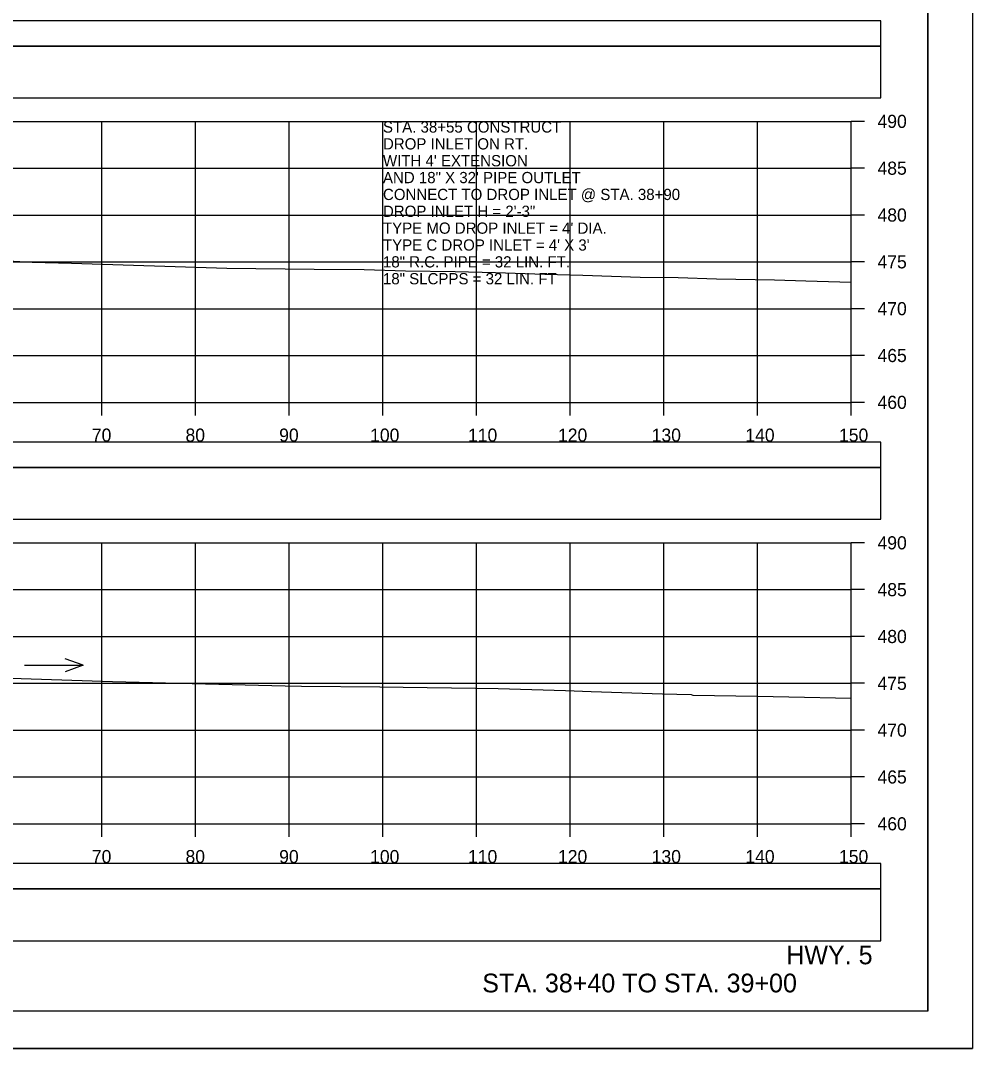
# Model space of a CAD drawing. Extents: x 1371057 to 1372761, y 380005 to 390517.
# Drawn here: x 1371955.5 to 1372057.1, y 381285.1 to 381394.9 of the extents above; entities that cross this region are included whole.
import ezdxf

# ---------------------------------------------------------------- set-up
doc = ezdxf.new("R2010")
doc.units = 0
for name, color, linetype in [('R_Axis', 7, 'Continuous'), ('R_Axis Annot', 7, 'Continuous'), ('R_Border', 7, 'Continuous'), ('R_Detour', 7, 'Continuous'), ('R_Dimension', 7, 'Continuous'), ('R_Draft', 7, 'Continuous'), ('R_Exist Surface', 7, 'Continuous'), ('R_Grid', 7, 'Continuous'), ('R_No Plot', 7, 'Continuous'), ('R_Water Annot', 7, 'Continuous')]:
    doc.layers.add(name, color=color, linetype=linetype)

msp = doc.modelspace()

# ---------------------------------------------------------------- linework, layer by layer
at = {"layer": 'R_Axis'}
for p, q in [((1372044.21, 381354.09), (1372044.21, 381384.09)), ((1372045.61, 381384.09), (1372044.21, 381384.09)), ((1372045.61, 381379.09), (1372044.21, 381379.09)), ((1372045.61, 381374.09), (1372044.21, 381374.09)), ((1372045.61, 381369.09), (1372044.21, 381369.09)), ((1372045.61, 381364.09), (1372044.21, 381364.09)), ((1372045.61, 381359.09), (1372044.21, 381359.09)), ((1371744.21, 381354.09), (1372044.21, 381354.09)), ((1371964.21, 381352.69), (1371964.21, 381354.09)), ((1371974.21, 381352.69), (1371974.21, 381354.09)), ((1371984.21, 381352.69), (1371984.21, 381354.09)), ((1371994.21, 381352.69), (1371994.21, 381354.09)), ((1372004.21, 381352.69), (1372004.21, 381354.09)), ((1372014.21, 381352.69), (1372014.21, 381354.09)), ((1372024.21, 381352.69), (1372024.21, 381354.09)), ((1372034.21, 381352.69), (1372034.21, 381354.09)), ((1372044.21, 381352.69), (1372044.21, 381354.09)), ((1372045.61, 381354.09), (1372044.21, 381354.09)), ((1372044.21, 381309.09), (1372044.21, 381339.09)), ((1372045.61, 381339.09), (1372044.21, 381339.09)), ((1372045.61, 381334.09), (1372044.21, 381334.09)), ((1372045.61, 381329.09), (1372044.21, 381329.09)), ((1372045.61, 381324.09), (1372044.21, 381324.09)), ((1372045.61, 381319.09), (1372044.21, 381319.09)), ((1372045.61, 381314.09), (1372044.21, 381314.09)), ((1371744.21, 381309.09), (1372044.21, 381309.09)), ((1371964.21, 381307.69), (1371964.21, 381309.09)), ((1371974.21, 381307.69), (1371974.21, 381309.09)), ((1371984.21, 381307.69), (1371984.21, 381309.09)), ((1371994.21, 381307.69), (1371994.21, 381309.09)), ((1372004.21, 381307.69), (1372004.21, 381309.09)), ((1372014.21, 381307.69), (1372014.21, 381309.09)), ((1372024.21, 381307.69), (1372024.21, 381309.09)), ((1372034.21, 381307.69), (1372034.21, 381309.09)), ((1372044.21, 381307.69), (1372044.21, 381309.09)), ((1372045.61, 381309.09), (1372044.21, 381309.09))]:
    msp.add_line(p, q, dxfattribs=at)
at = {"layer": 'R_Border'}
for q in [(1372052.39, 381494.55), (1371736.21, 381289.09)]:
    msp.add_line((1372052.39, 381289.09), q, dxfattribs=at)
at = {"layer": 'R_Detour'}
for points in [[(1371741.06, 381392.13), (1372047.37, 381392.13), (1372047.37, 381394.84), (1371741.06, 381394.84)], [(1371741.06, 381347.13), (1372047.37, 381347.13), (1372047.37, 381349.84), (1371741.06, 381349.84)], [(1371741.06, 381302.13), (1372047.37, 381302.13), (1372047.37, 381304.84), (1371741.06, 381304.84)]]:
    msp.add_lwpolyline(points, close=True, dxfattribs=at)
at = {"layer": 'R_Dimension'}
for points in [[(1371741.06, 381386.61), (1372047.37, 381386.61), (1372047.37, 381392.13), (1371741.06, 381392.13)], [(1371741.06, 381341.61), (1372047.37, 381341.61), (1372047.37, 381347.13), (1371741.06, 381347.13)], [(1371741.06, 381296.61), (1372047.37, 381296.61), (1372047.37, 381302.13), (1371741.06, 381302.13)]]:
    msp.add_lwpolyline(points, close=True, dxfattribs=at)
at = {"layer": 'R_Exist Surface'}
for points in [[(1371952.18, 381369.32), (1371956.75, 381369.06), (1371960.94, 381368.95), (1371977.54, 381368.43), (1371986.87, 381368.32), (1371992.22, 381368.26), (1371996.63, 381368.13), (1372001.93, 381368.06), (1372006.22, 381367.96), (1372011.49, 381367.78), (1372015.54, 381367.67), (1372021.68, 381367.47), (1372025.71, 381367.41), (1372029.81, 381367.28), (1372036, 381367.17), (1372039.37, 381367.05), (1372044.21, 381366.92)], [(1371953.4, 381324.66), (1371965.34, 381324.29), (1371983.77, 381323.81), (1371985.52, 381323.78), (1371993.88, 381323.72), (1371996.36, 381323.68), (1372004.08, 381323.58), (1372006.5, 381323.54), (1372013.71, 381323.31), (1372016.43, 381323.2), (1372024.05, 381322.96), (1372027.1, 381322.88), (1372027.3, 381322.83), (1372034.21, 381322.72), (1372037.56, 381322.66), (1372044.21, 381322.49)]]:
    msp.add_lwpolyline(points, dxfattribs=at)
at = {"layer": 'R_Grid'}
for p, q in [((1371744.21, 381384.09), (1372044.21, 381384.09)), ((1371964.21, 381354.09), (1371964.21, 381384.09)), ((1371974.21, 381354.09), (1371974.21, 381384.09)), ((1371984.21, 381354.09), (1371984.21, 381384.09)), ((1371994.21, 381354.09), (1371994.21, 381384.09)), ((1372004.21, 381354.09), (1372004.21, 381384.09)), ((1372014.21, 381354.09), (1372014.21, 381384.09)), ((1372024.21, 381354.09), (1372024.21, 381384.09)), ((1372034.21, 381354.09), (1372034.21, 381384.09)), ((1372044.21, 381354.09), (1372044.21, 381384.09)), ((1371744.21, 381379.09), (1372044.21, 381379.09)), ((1371744.21, 381374.09), (1372044.21, 381374.09)), ((1371744.21, 381369.09), (1372044.21, 381369.09)), ((1371744.21, 381364.09), (1372044.21, 381364.09)), ((1371744.21, 381359.09), (1372044.21, 381359.09)), ((1371744.21, 381354.09), (1372044.21, 381354.09)), ((1371744.21, 381339.09), (1372044.21, 381339.09)), ((1371964.21, 381309.09), (1371964.21, 381339.09)), ((1371974.21, 381309.09), (1371974.21, 381339.09)), ((1371984.21, 381309.09), (1371984.21, 381339.09)), ((1371994.21, 381309.09), (1371994.21, 381339.09)), ((1372004.21, 381309.09), (1372004.21, 381339.09)), ((1372014.21, 381309.09), (1372014.21, 381339.09)), ((1372024.21, 381309.09), (1372024.21, 381339.09)), ((1372034.21, 381309.09), (1372034.21, 381339.09)), ((1372044.21, 381309.09), (1372044.21, 381339.09)), ((1371744.21, 381334.09), (1372044.21, 381334.09)), ((1371744.21, 381329.09), (1372044.21, 381329.09)), ((1371744.21, 381324.09), (1372044.21, 381324.09)), ((1371744.21, 381319.09), (1372044.21, 381319.09)), ((1371744.21, 381314.09), (1372044.21, 381314.09)), ((1371744.21, 381309.09), (1372044.21, 381309.09))]:
    msp.add_line(p, q, dxfattribs=at)
at = {"layer": 'R_No Plot'}
msp.add_line((1371723.81, 381285.11), (1372057.14, 381285.11), dxfattribs=at)
for points in [[(1371723.8, 381498.44), (1372057.14, 381498.44), (1372057.14, 381285.1), (1371723.8, 381285.1)], [(1371970.13, 381494.55), (1371989.75, 381494.55), (1371989.75, 381484.67), (1372005.86, 381484.67), (1372029.06, 381484.67), (1372029.18, 381456.51), (1372052.39, 381456.51), (1372052.39, 381289.09), (1371736.21, 381289.09), (1371736.21, 381494.55)]]:
    msp.add_lwpolyline(points, close=True, dxfattribs=at)
at = {"layer": 'R_Water Annot'}
for p, q in [((1371962.22, 381326.02), (1371960.29, 381326.72)), ((1371955.93, 381326.02), (1371962.22, 381326.02)), ((1371962.22, 381326.02), (1371960.29, 381325.32))]:
    msp.add_line(p, q, dxfattribs=at)

# ---------------------------------------------------------------- texts
at = {"layer": 'R_Axis Annot'}
for s, p in [('490', (1372047.01, 381383.39)), ('485', (1372047.01, 381378.39)), ('480', (1372047.01, 381373.39)), ('475', (1372047.01, 381368.39)), ('470', (1372047.01, 381363.39)), ('465', (1372047.01, 381358.39)), ('460', (1372047.01, 381353.39)), ('70', (1371963.13, 381349.89)), ('80', (1371973.13, 381349.89)), ('90', (1371983.13, 381349.89)), ('100', (1371992.84, 381349.89)), ('110', (1372003.29, 381349.89)), ('120', (1372012.9, 381349.89)), ('130', (1372022.9, 381349.89)), ('140', (1372032.9, 381349.89)), ('150', (1372042.9, 381349.89)), ('490', (1372047.01, 381338.39)), ('485', (1372047.01, 381333.39)), ('480', (1372047.01, 381328.39)), ('475', (1372047.01, 381323.39)), ('470', (1372047.01, 381318.39)), ('465', (1372047.01, 381313.39)), ('460', (1372047.01, 381308.39)), ('70', (1371963.13, 381304.89)), ('80', (1371973.13, 381304.89)), ('90', (1371983.13, 381304.89)), ('100', (1371992.84, 381304.89)), ('110', (1372003.29, 381304.89)), ('120', (1372012.9, 381304.89)), ('130', (1372022.9, 381304.89)), ('140', (1372032.9, 381304.89)), ('150', (1372042.9, 381304.89))]:
    msp.add_text(s, height=1.4, dxfattribs=at).set_placement(p)
at = {"layer": 'R_Draft'}
for s, p in [('HWY. 5', (1372037.27, 381294.09)), ('STA. 38+40 TO STA. 39+00', (1372004.81, 381291.09))]:
    msp.add_text(s, height=2, dxfattribs=at).set_placement(p)
at = {"layer": 'R_Water Annot'}
for s, p in [('STA. 38+55 CONSTRUCT', (1371994.21, 381382.89)), ('DROP INLET ON RT.', (1371994.21, 381381.09)), ("WITH 4' EXTENSION", (1371994.21, 381379.29)), ('AND 18" X 32\' PIPE OUTLET', (1371994.21, 381377.49)), ('CONNECT TO DROP INLET @ STA. 38+90', (1371994.21, 381375.69)), ('DROP INLET H = 2\'-3"', (1371994.21, 381373.89)), ("TYPE MO DROP INLET = 4' DIA.", (1371994.21, 381372.09)), ("TYPE C DROP INLET = 4' X 3'", (1371994.21, 381370.29)), ('18" R.C. PIPE = 32 LIN. FT.', (1371994.21, 381368.49)), ('18" SLCPPS = 32 LIN. FT', (1371994.21, 381366.69))]:
    msp.add_text(s, height=1.2, dxfattribs=at).set_placement(p)

doc.saveas('drawing.dxf')
